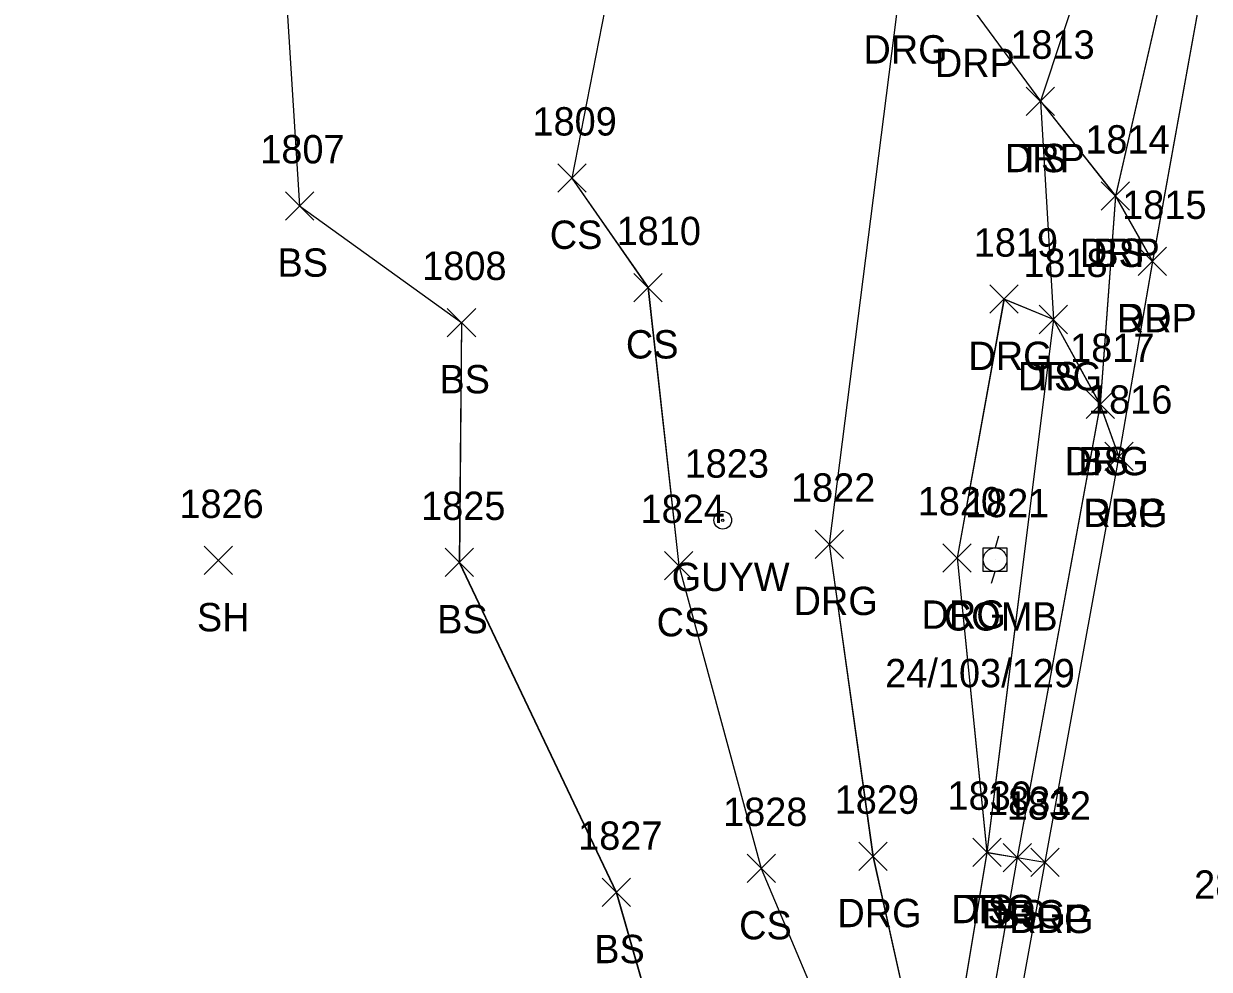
# Model space of a CAD drawing. Extents: x 1554668 to 1563881, y 831386 to 834374.
# Drawn here: x 1562167.8 to 1562251.5, y 832658.8 to 832725.5 of the extents above; entities that cross this region are included whole.
import ezdxf

# ---------------------------------------------------------------- set-up
doc = ezdxf.new("R2010")
doc.units = 0
for name, color, linetype in [('L_A', 7, 'Continuous'), ('L_I', 7, 'Continuous'), ('L_TIC', 7, 'Continuous'), ('LELB', 7, 'Continuous'), ('P_A', 7, 'Continuous'), ('P_I', 7, 'Continuous'), ('P_TIC', 7, 'Continuous'), ('PET', 7, 'Continuous'), ('R_A', 7, 'Continuous'), ('R_I', 7, 'Continuous'), ('R_TIC', 7, 'Continuous'), ('RDG', 7, 'Continuous'), ('RDP', 7, 'Continuous'), ('U_A', 7, 'Continuous'), ('U_C', 7, 'Continuous'), ('U_I', 7, 'Continuous'), ('UP', 7, 'Continuous'), ('UPGW', 7, 'Continuous')]:
    doc.layers.add(name, color=color, linetype=linetype)

msp = doc.modelspace()

# ---------------------------------------------------------------- linework, layer by layer
at = {"layer": 'L_TIC'}
for points in [[(1562238.571, 832719.027), (1562240.571, 832721.027)], [(1562240.571, 832719.027), (1562238.571, 832721.027)], [(1562205.508, 832713.613), (1562207.508, 832715.613)], [(1562207.508, 832713.613), (1562205.508, 832715.613)], [(1562243.861, 832712.342), (1562245.861, 832714.342)], [(1562245.861, 832712.342), (1562243.861, 832714.342)], [(1562186.295, 832711.648), (1562188.295, 832713.648)], [(1562188.295, 832711.648), (1562186.295, 832713.648)], [(1562210.878, 832705.879), (1562212.878, 832707.879)], [(1562212.878, 832705.879), (1562210.878, 832707.879)], [(1562197.722, 832703.419), (1562199.722, 832705.419)], [(1562199.722, 832703.419), (1562197.722, 832705.419)], [(1562239.485, 832703.631), (1562241.485, 832705.631)], [(1562241.485, 832703.631), (1562239.485, 832705.631)], [(1562242.789, 832697.638), (1562244.789, 832699.638)], [(1562244.789, 832697.638), (1562242.789, 832699.638)], [(1562180.566, 832686.626), (1562182.566, 832688.626)], [(1562182.566, 832686.626), (1562180.566, 832688.626)], [(1562197.565, 832686.485), (1562199.565, 832688.485)], [(1562199.565, 832686.485), (1562197.565, 832688.485)], [(1562213.046, 832686.271), (1562215.046, 832688.271)], [(1562215.046, 832686.271), (1562213.046, 832688.271)], [(1562234.792, 832666.031), (1562236.792, 832668.031)], [(1562236.792, 832666.031), (1562234.792, 832668.031)], [(1562236.929, 832665.662), (1562238.929, 832667.662)], [(1562238.929, 832665.662), (1562236.929, 832667.662)], [(1562218.869, 832664.89), (1562220.869, 832666.89)], [(1562220.869, 832664.89), (1562218.869, 832666.89)], [(1562208.645, 832663.207), (1562210.645, 832665.207)], [(1562210.645, 832663.207), (1562208.645, 832665.207)]]:
    msp.add_lwpolyline(points, dxfattribs=at)
at = {"layer": 'LELB'}
for points in [[(1562200.319, 833009.343), (1562250.032, 832998.896), (1562276.392, 832991.44), (1562294.256, 832987.301), (1562294.509, 832979.714), (1562291.449, 832962.579), (1562287.107, 832937.999), (1562279.03, 832891.065), (1562273.318, 832854.566), (1562271.935, 832849.042), (1562264.251, 832813.847), (1562264.727, 832800.258), (1562260.831, 832790.587), (1562254.987, 832763.768), (1562255.206, 832758.108), (1562250.522, 832738.023), (1562244.864, 832713.348), (1562243.792, 832698.645), (1562237.934, 832666.666), (1562233.862, 832643.438), (1562225.508, 832600.623), (1562224.97, 832593.616)], [(1562200.319, 833009.343), (1562250.032, 832998.896), (1562276.392, 832991.44), (1562294.256, 832987.301), (1562294.509, 832979.714), (1562291.449, 832962.579), (1562287.107, 832937.999), (1562279.03, 832891.065), (1562273.318, 832854.566), (1562271.935, 832849.042), (1562264.251, 832813.847), (1562264.727, 832800.258), (1562260.831, 832790.587), (1562254.987, 832763.768), (1562255.206, 832758.108), (1562250.522, 832738.023), (1562244.864, 832713.348), (1562243.792, 832698.645), (1562237.934, 832666.666), (1562233.862, 832643.438), (1562225.508, 832600.623), (1562224.97, 832593.616)], [(1562200.319, 833009.343), (1562250.032, 832998.896), (1562276.392, 832991.44), (1562294.256, 832987.301), (1562294.509, 832979.714), (1562291.449, 832962.579), (1562287.107, 832937.999), (1562279.03, 832891.065), (1562273.318, 832854.566), (1562271.935, 832849.042), (1562264.251, 832813.847), (1562264.727, 832800.258), (1562260.831, 832790.587), (1562254.987, 832763.768), (1562255.206, 832758.108), (1562250.522, 832738.023), (1562244.864, 832713.348), (1562243.792, 832698.645), (1562237.934, 832666.666), (1562233.862, 832643.438), (1562225.508, 832600.623), (1562224.97, 832593.616)], [(1562200.322, 833009.343), (1562250.033, 832998.897), (1562276.395, 832991.44), (1562294.255, 832987.301), (1562294.509, 832979.715), (1562291.449, 832962.579), (1562287.105, 832937.996), (1562279.025, 832891.061), (1562273.315, 832854.563), (1562271.934, 832849.035), (1562264.247, 832813.846), (1562264.723, 832800.257), (1562260.828, 832790.584), (1562254.984, 832763.768), (1562255.203, 832758.102), (1562250.519, 832738.023), (1562244.861, 832713.342), (1562243.789, 832698.638), (1562237.929, 832666.662), (1562233.855, 832643.437), (1562225.504, 832600.622), (1562224.967, 832593.618)], [(1562218.14, 832900.292), (1562218.268, 832876.803), (1562215.95, 832854.332), (1562215.695, 832828.477), (1562203.989, 832802.393), (1562207.068, 832776.241), (1562211.153, 832738.443), (1562206.508, 832714.613), (1562211.878, 832706.879), (1562214.046, 832687.271), (1562219.869, 832665.89), (1562225.537, 832652.434), (1562223.306, 832642.664), (1562220.942, 832627.463), (1562218.599, 832610.018), (1562223.013, 832601.103)], [(1562218.139, 832900.297), (1562218.274, 832876.808), (1562215.955, 832854.338), (1562215.7, 832828.484), (1562203.993, 832802.4), (1562207.072, 832776.244), (1562211.155, 832738.444), (1562206.51, 832714.612), (1562211.882, 832706.883), (1562214.049, 832687.275), (1562219.873, 832665.886), (1562225.54, 832652.432), (1562223.311, 832642.661), (1562220.948, 832627.466), (1562218.602, 832610.014), (1562223.016, 832601.097)], [(1562218.139, 832900.297), (1562218.274, 832876.808), (1562215.955, 832854.338), (1562215.7, 832828.484), (1562203.993, 832802.4), (1562207.072, 832776.244), (1562211.155, 832738.444), (1562206.51, 832714.612), (1562211.882, 832706.883), (1562214.049, 832687.275), (1562219.873, 832665.886), (1562225.54, 832652.432), (1562223.311, 832642.661), (1562220.948, 832627.466), (1562218.602, 832610.014), (1562223.016, 832601.097)], [(1562218.139, 832900.297), (1562218.274, 832876.808), (1562215.955, 832854.338), (1562215.7, 832828.484), (1562203.993, 832802.4), (1562207.072, 832776.244), (1562211.155, 832738.444), (1562206.51, 832714.612), (1562211.882, 832706.883), (1562214.049, 832687.275), (1562219.873, 832665.886), (1562225.54, 832652.432), (1562223.311, 832642.661), (1562220.948, 832627.466), (1562218.602, 832610.014), (1562223.016, 832601.097)], [(1562257.146, 832792.191), (1562250.632, 832765.696), (1562249.746, 832756.735), (1562245.942, 832739.285), (1562239.571, 832720.027), (1562240.485, 832704.631), (1562235.792, 832667.031), (1562232.401, 832646.664), (1562223.013, 832601.103), (1562221.104, 832590.266)], [(1562257.149, 832792.196), (1562250.635, 832765.702), (1562249.749, 832756.74), (1562245.946, 832739.286), (1562239.574, 832720.029), (1562240.488, 832704.636), (1562235.794, 832667.026), (1562232.403, 832646.663), (1562223.016, 832601.097), (1562221.107, 832590.266)], [(1562257.149, 832792.196), (1562250.635, 832765.702), (1562249.749, 832756.74), (1562245.946, 832739.286), (1562239.574, 832720.029), (1562240.488, 832704.636), (1562235.794, 832667.026), (1562232.403, 832646.663), (1562223.016, 832601.097), (1562221.107, 832590.266)], [(1562257.149, 832792.196), (1562250.635, 832765.702), (1562249.749, 832756.74), (1562245.946, 832739.286), (1562239.574, 832720.029), (1562240.488, 832704.636), (1562235.794, 832667.026), (1562232.403, 832646.663), (1562223.016, 832601.097), (1562221.107, 832590.266)], [(1562185.625, 832739.135), (1562187.295, 832712.648), (1562198.722, 832704.419), (1562198.565, 832687.485), (1562209.645, 832664.207), (1562213.312, 832651.394), (1562214.739, 832645.481), (1562200.539, 832648.189), (1562185.195, 832650.741)], [(1562185.627, 832739.136), (1562187.3, 832712.655), (1562198.726, 832704.425), (1562198.569, 832687.482), (1562209.648, 832664.205), (1562213.316, 832651.393), (1562214.739, 832645.481), (1562200.541, 832648.189), (1562185.196, 832650.741)], [(1562185.627, 832739.136), (1562187.3, 832712.655), (1562198.726, 832704.425), (1562198.569, 832687.482), (1562209.648, 832664.205), (1562213.316, 832651.393), (1562214.739, 832645.481), (1562200.541, 832648.189), (1562185.196, 832650.741)], [(1562185.627, 832739.136), (1562187.3, 832712.655), (1562198.726, 832704.425), (1562198.569, 832687.482), (1562209.648, 832664.205), (1562213.316, 832651.393), (1562214.739, 832645.481), (1562200.541, 832648.189), (1562185.196, 832650.741)]]:
    msp.add_lwpolyline(points, dxfattribs=at)
at = {"layer": 'P_TIC'}
for points in [[(1562246.466, 832707.729), (1562248.466, 832709.729)], [(1562248.466, 832707.729), (1562246.466, 832709.729)], [(1562244.108, 832693.982), (1562246.108, 832695.982)], [(1562246.108, 832693.982), (1562244.108, 832695.982)], [(1562238.881, 832665.33), (1562240.881, 832667.33)], [(1562240.881, 832665.33), (1562238.881, 832667.33)]]:
    msp.add_lwpolyline(points, dxfattribs=at)
at = {"layer": 'PET'}
for points in [[(1562273.885, 832849.078), (1562267.566, 832813.604), (1562265.603, 832799.939), (1562262.702, 832788.044), (1562256.455, 832758.513), (1562247.466, 832708.729), (1562245.108, 832694.982), (1562239.881, 832666.33), (1562235.287, 832641.147), (1562227.424, 832596.073), (1562223.217, 832566.02), (1562217.529, 832537.337), (1562210.223, 832493.736), (1562206.372, 832468.814), (1562200.609, 832439.099), (1562195.311, 832417.053), (1562190.426, 832389.216), (1562186.216, 832366.423), (1562178.76, 832327.806), (1562173.255, 832299.979), (1562167.833, 832271.729)], [(1562273.888, 832849.082), (1562267.57, 832813.605), (1562265.607, 832799.938), (1562262.705, 832788.043), (1562256.457, 832758.517), (1562247.47, 832708.736), (1562245.111, 832694.99), (1562239.884, 832666.33), (1562235.289, 832641.147), (1562227.427, 832596.074), (1562223.221, 832566.018), (1562217.533, 832537.341), (1562210.228, 832493.73), (1562206.377, 832468.81), (1562200.609, 832439.095), (1562195.315, 832417.049), (1562190.426, 832389.208), (1562186.219, 832366.417), (1562178.763, 832327.803), (1562173.257, 832299.981), (1562167.837, 832271.725)], [(1562273.888, 832849.082), (1562267.57, 832813.605), (1562265.607, 832799.938), (1562262.705, 832788.043), (1562256.457, 832758.517), (1562247.47, 832708.736), (1562245.111, 832694.99), (1562239.884, 832666.33), (1562235.289, 832641.147), (1562227.427, 832596.074), (1562223.221, 832566.018), (1562217.533, 832537.341), (1562210.228, 832493.73), (1562206.377, 832468.81), (1562200.609, 832439.095), (1562195.315, 832417.049), (1562190.426, 832389.208), (1562186.219, 832366.417), (1562178.763, 832327.803), (1562173.257, 832299.981), (1562167.837, 832271.725)], [(1562273.888, 832849.082), (1562267.57, 832813.605), (1562265.607, 832799.938), (1562262.705, 832788.043), (1562256.457, 832758.517), (1562247.47, 832708.736), (1562245.111, 832694.99), (1562239.884, 832666.33), (1562235.289, 832641.147), (1562227.427, 832596.074), (1562223.221, 832566.018), (1562217.533, 832537.341), (1562210.228, 832493.73), (1562206.377, 832468.81), (1562200.609, 832439.095), (1562195.315, 832417.049), (1562190.426, 832389.208), (1562186.219, 832366.417), (1562178.763, 832327.803), (1562173.257, 832299.981), (1562167.837, 832271.725)]]:
    msp.add_lwpolyline(points, dxfattribs=at)
at = {"layer": 'R_TIC'}
for points in [[(1562238.571, 832719.027), (1562240.571, 832721.027)], [(1562240.571, 832719.027), (1562238.571, 832721.027)], [(1562243.861, 832712.342), (1562245.861, 832714.342)], [(1562245.861, 832712.342), (1562243.861, 832714.342)], [(1562246.466, 832707.729), (1562248.466, 832709.729)], [(1562248.466, 832707.729), (1562246.466, 832709.729)], [(1562235.997, 832705.067), (1562237.997, 832707.067)], [(1562237.997, 832705.067), (1562235.997, 832707.067)], [(1562239.485, 832703.631), (1562241.485, 832705.631)], [(1562241.485, 832703.631), (1562239.485, 832705.631)], [(1562242.789, 832697.638), (1562244.789, 832699.638)], [(1562244.789, 832697.638), (1562242.789, 832699.638)], [(1562244.108, 832693.982), (1562246.108, 832695.982)], [(1562246.108, 832693.982), (1562244.108, 832695.982)], [(1562223.664, 832687.775), (1562225.664, 832689.775)], [(1562225.664, 832687.775), (1562223.664, 832689.775)], [(1562232.689, 832686.807), (1562234.689, 832688.807)], [(1562234.689, 832686.807), (1562232.689, 832688.807)], [(1562226.753, 832665.748), (1562228.753, 832667.748)], [(1562228.753, 832665.748), (1562226.753, 832667.748)], [(1562234.792, 832666.031), (1562236.792, 832668.031)], [(1562236.792, 832666.031), (1562234.792, 832668.031)], [(1562236.929, 832665.662), (1562238.929, 832667.662)], [(1562238.929, 832665.662), (1562236.929, 832667.662)], [(1562238.881, 832665.33), (1562240.881, 832667.33)], [(1562240.881, 832665.33), (1562238.881, 832667.33)]]:
    msp.add_lwpolyline(points, dxfattribs=at)
at = {"layer": 'RDG'}
for points in [[(1562178.329, 832849.013), (1562178.773, 832830.356), (1562196.752, 832830.897), (1562215.695, 832828.477), (1562226.372, 832813.472), (1562225.814, 832794.259), (1562224.697, 832768.927), (1562226.017, 832741.204), (1562229.592, 832727.694), (1562224.664, 832688.775), (1562227.753, 832666.748), (1562230.729, 832653.346), (1562232.401, 832646.664), (1562233.855, 832643.437), (1562235.287, 832641.147)], [(1562178.336, 832849.018), (1562178.777, 832830.361), (1562196.753, 832830.898), (1562215.7, 832828.484), (1562226.377, 832813.479), (1562225.818, 832794.264), (1562224.701, 832768.933), (1562226.02, 832741.204), (1562229.595, 832727.694), (1562224.668, 832688.779), (1562227.756, 832666.747), (1562230.732, 832653.344), (1562232.403, 832646.663), (1562233.862, 832643.438), (1562235.289, 832641.147)], [(1562178.336, 832849.018), (1562178.777, 832830.361), (1562196.753, 832830.898), (1562215.7, 832828.484), (1562226.377, 832813.479), (1562225.818, 832794.264), (1562224.701, 832768.933), (1562226.02, 832741.204), (1562229.595, 832727.694), (1562224.668, 832688.779), (1562227.756, 832666.747), (1562230.732, 832653.344), (1562232.403, 832646.663), (1562233.862, 832643.438), (1562235.289, 832641.147)], [(1562178.336, 832849.018), (1562178.777, 832830.361), (1562196.753, 832830.898), (1562215.7, 832828.484), (1562226.377, 832813.479), (1562225.818, 832794.264), (1562224.701, 832768.933), (1562226.02, 832741.204), (1562229.595, 832727.694), (1562224.668, 832688.779), (1562227.756, 832666.747), (1562230.732, 832653.344), (1562232.403, 832646.663), (1562233.862, 832643.438), (1562235.289, 832641.147)], [(1562245.108, 832694.982), (1562243.789, 832698.638), (1562240.485, 832704.631), (1562236.997, 832706.067), (1562233.689, 832687.807), (1562235.792, 832667.031), (1562237.929, 832666.662), (1562239.881, 832666.33)], [(1562245.111, 832694.99), (1562243.792, 832698.645), (1562240.488, 832704.636), (1562237, 832706.066), (1562233.692, 832687.81), (1562235.794, 832667.026), (1562237.934, 832666.666), (1562239.884, 832666.33)], [(1562245.111, 832694.99), (1562243.792, 832698.645), (1562240.488, 832704.636), (1562237, 832706.066), (1562233.692, 832687.81), (1562235.794, 832667.026), (1562237.934, 832666.666), (1562239.884, 832666.33)], [(1562245.111, 832694.99), (1562243.792, 832698.645), (1562240.488, 832704.636), (1562237, 832706.066), (1562233.692, 832687.81), (1562235.794, 832667.026), (1562237.934, 832666.666), (1562239.884, 832666.33)]]:
    msp.add_lwpolyline(points, dxfattribs=at)
at = {"layer": 'RDP'}
for points in [[(1562256.455, 832758.513), (1562255.203, 832758.102), (1562249.746, 832756.735), (1562242.181, 832741.488), (1562234.632, 832726.743), (1562239.571, 832720.027), (1562244.861, 832713.342), (1562247.466, 832708.729)], [(1562256.457, 832758.517), (1562255.206, 832758.108), (1562249.749, 832756.74), (1562242.184, 832741.49), (1562234.635, 832726.747), (1562239.574, 832720.029), (1562244.864, 832713.348), (1562247.47, 832708.736)], [(1562256.457, 832758.517), (1562255.206, 832758.108), (1562249.749, 832756.74), (1562242.184, 832741.49), (1562234.635, 832726.747), (1562239.574, 832720.029), (1562244.864, 832713.348), (1562247.47, 832708.736)], [(1562256.457, 832758.517), (1562255.206, 832758.108), (1562249.749, 832756.74), (1562242.184, 832741.49), (1562234.635, 832726.747), (1562239.574, 832720.029), (1562244.864, 832713.348), (1562247.47, 832708.736)]]:
    msp.add_lwpolyline(points, dxfattribs=at)
at = {"layer": 'UP'}
for p, q in [((1562236.622, 832689.347), (1562236.372, 832688.514)), ((1562235.539, 832686.847), (1562235.539, 832688.514)), ((1562235.539, 832688.514), (1562237.206, 832688.514)), ((1562237.206, 832688.514), (1562237.206, 832686.847)), ((1562236.372, 832687.68), (1562236.372, 832687.68)), ((1562237.206, 832686.847), (1562235.539, 832686.847)), ((1562236.122, 832686.014), (1562236.372, 832686.847))]:
    msp.add_line(p, q, dxfattribs=at)
msp.add_circle((1562236.372, 832687.68), 0.833, dxfattribs=at)
at = {"layer": 'UPGW'}
for radius in [0.625, 0.0833]:
    msp.add_circle((1562217.157, 832690.469), radius, dxfattribs=at)

# ---------------------------------------------------------------- texts
at = {"layer": 'L_A'}
for s, p in [('TS', (1562237.981, 832715.027)), ('CS', (1562204.949, 832709.613)), ('BS', (1562243.301, 832708.342)), ('BS', (1562185.736, 832707.648)), ('CS', (1562210.319, 832701.879)), ('BS', (1562197.163, 832699.419)), ('TS', (1562238.894, 832699.631)), ('BS', (1562242.23, 832693.638)), ('SH', (1562180.054, 832682.626)), ('BS', (1562197.006, 832682.485)), ('CS', (1562212.487, 832682.271)), ('TS', (1562234.201, 832662.031)), ('BS', (1562236.37, 832661.662)), ('CS', (1562218.31, 832660.89)), ('BS', (1562208.085, 832659.207))]:
    msp.add_text(s, height=2, dxfattribs=at).set_placement(p)
at = {"layer": 'L_I'}
for s, p in [('1813', (1562237.445, 832723.027)), ('1809', (1562203.728, 832717.613)), ('1814', (1562242.735, 832716.342)), ('1807', (1562184.524, 832715.648)), ('1810', (1562209.666, 832709.879)), ('1808', (1562195.95, 832707.419)), ('1818', (1562238.359, 832707.631)), ('1817', (1562241.663, 832701.638)), ('1826', (1562178.818, 832690.626)), ('1825', (1562195.872, 832690.485)), ('1824', (1562211.353, 832690.271)), ('1830', (1562233.012, 832670.031)), ('1831', (1562235.803, 832669.662)), ('1828', (1562217.176, 832668.89)), ('1827', (1562206.952, 832667.207))]:
    msp.add_text(s, height=2, dxfattribs=at).set_placement(p)
at = {"layer": 'P_A'}
for p in [(1562244.954, 832703.729), (1562242.596, 832689.982), (1562237.369, 832661.33)]:
    msp.add_text('RDP', height=2, dxfattribs=at).set_placement(p)
at = {"layer": 'P_I'}
for s, p in [('1815', (1562245.34, 832711.729)), ('1816', (1562242.927, 832697.982)), ('1832', (1562237.188, 832669.33)), ('2812', (1562250.411, 832663.756))]:
    msp.add_text(s, height=2, dxfattribs=at).set_placement(p)
at = {"layer": 'R_A'}
for s, p in [('DRG', (1562227.08, 832722.694)), ('DRP', (1562232.12, 832721.743)), ('DRP', (1562237.059, 832715.027)), ('DRP', (1562242.349, 832708.342)), ('DRP', (1562244.954, 832703.729)), ('DRG', (1562234.485, 832701.067)), ('DRG', (1562237.973, 832699.631)), ('DRG', (1562241.277, 832693.638)), ('DRG', (1562242.596, 832689.982)), ('DRG', (1562222.153, 832683.775)), ('DRG', (1562231.177, 832682.807)), ('DRG', (1562225.241, 832661.748)), ('DRG', (1562233.28, 832662.031)), ('DRG', (1562235.417, 832661.662)), ('DRG', (1562237.369, 832661.33))]:
    msp.add_text(s, height=2, dxfattribs=at).set_placement(p)
at = {"layer": 'R_I'}
for s, p in [('1813', (1562237.445, 832723.027)), ('1814', (1562242.735, 832716.342)), ('1815', (1562245.34, 832711.729)), ('1819', (1562234.863, 832709.067)), ('1818', (1562238.359, 832707.631)), ('1817', (1562241.663, 832701.638)), ('1816', (1562242.927, 832697.982)), ('1822', (1562221.972, 832691.775)), ('1820', (1562230.91, 832690.807)), ('1829', (1562225.052, 832669.748)), ('1830', (1562233.012, 832670.031)), ('1831', (1562235.803, 832669.662)), ('1832', (1562237.188, 832669.33))]:
    msp.add_text(s, height=2, dxfattribs=at).set_placement(p)
at = {"layer": 'U_A'}
for s, p in [('GUYW', (1562213.551, 832685.469)), ('COMB', (1562232.758, 832682.68))]:
    msp.add_text(s, height=2, dxfattribs=at).set_placement(p)
at = {"layer": 'U_C'}
msp.add_text('24/103/129', height=2, dxfattribs=at).set_placement((1562228.616, 832678.68))
at = {"layer": 'U_I'}
for s, p in [('1823', (1562214.464, 832693.469)), ('1821', (1562234.246, 832690.68))]:
    msp.add_text(s, height=2, dxfattribs=at).set_placement(p)

doc.saveas('drawing.dxf')
